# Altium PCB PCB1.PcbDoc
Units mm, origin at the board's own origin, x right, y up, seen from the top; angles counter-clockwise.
Board outline 152.4 x 101.6 mm, 2 copper layers (Top Layer, Bottom Layer); 9 components, 11 nets, 39 pads, 4 vias.
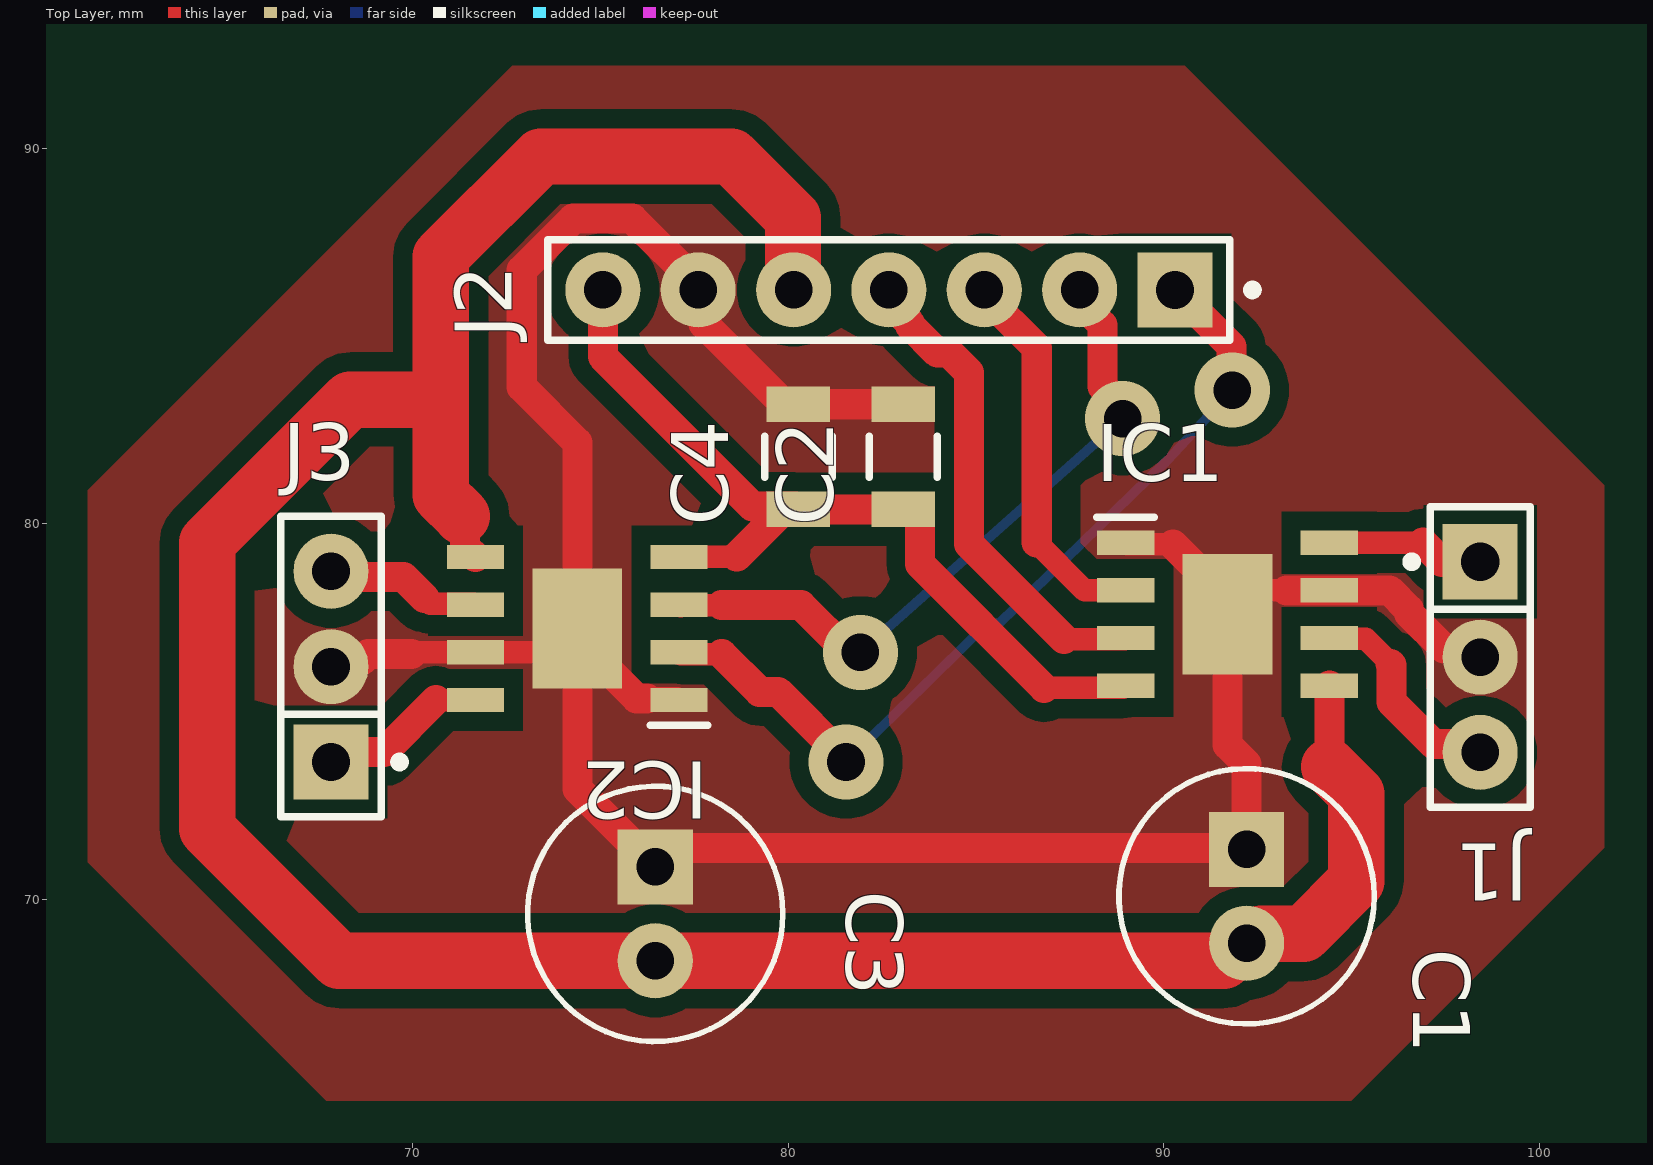
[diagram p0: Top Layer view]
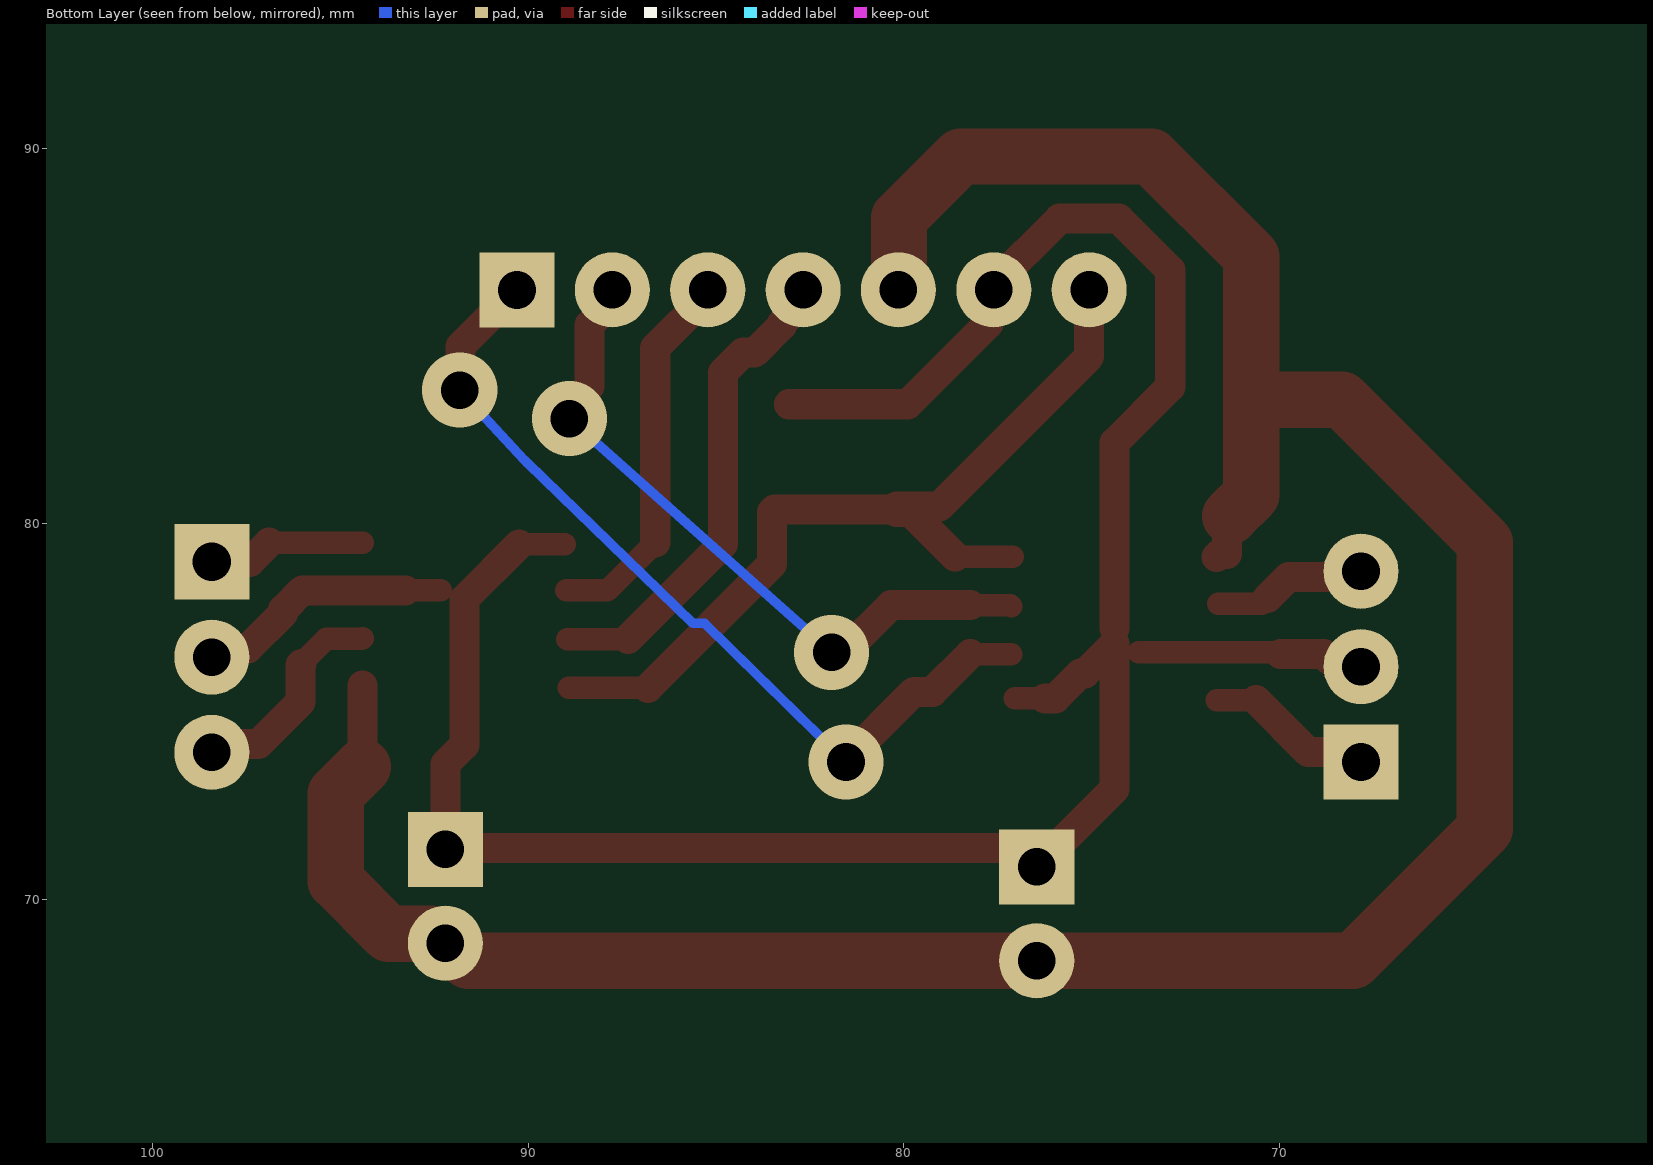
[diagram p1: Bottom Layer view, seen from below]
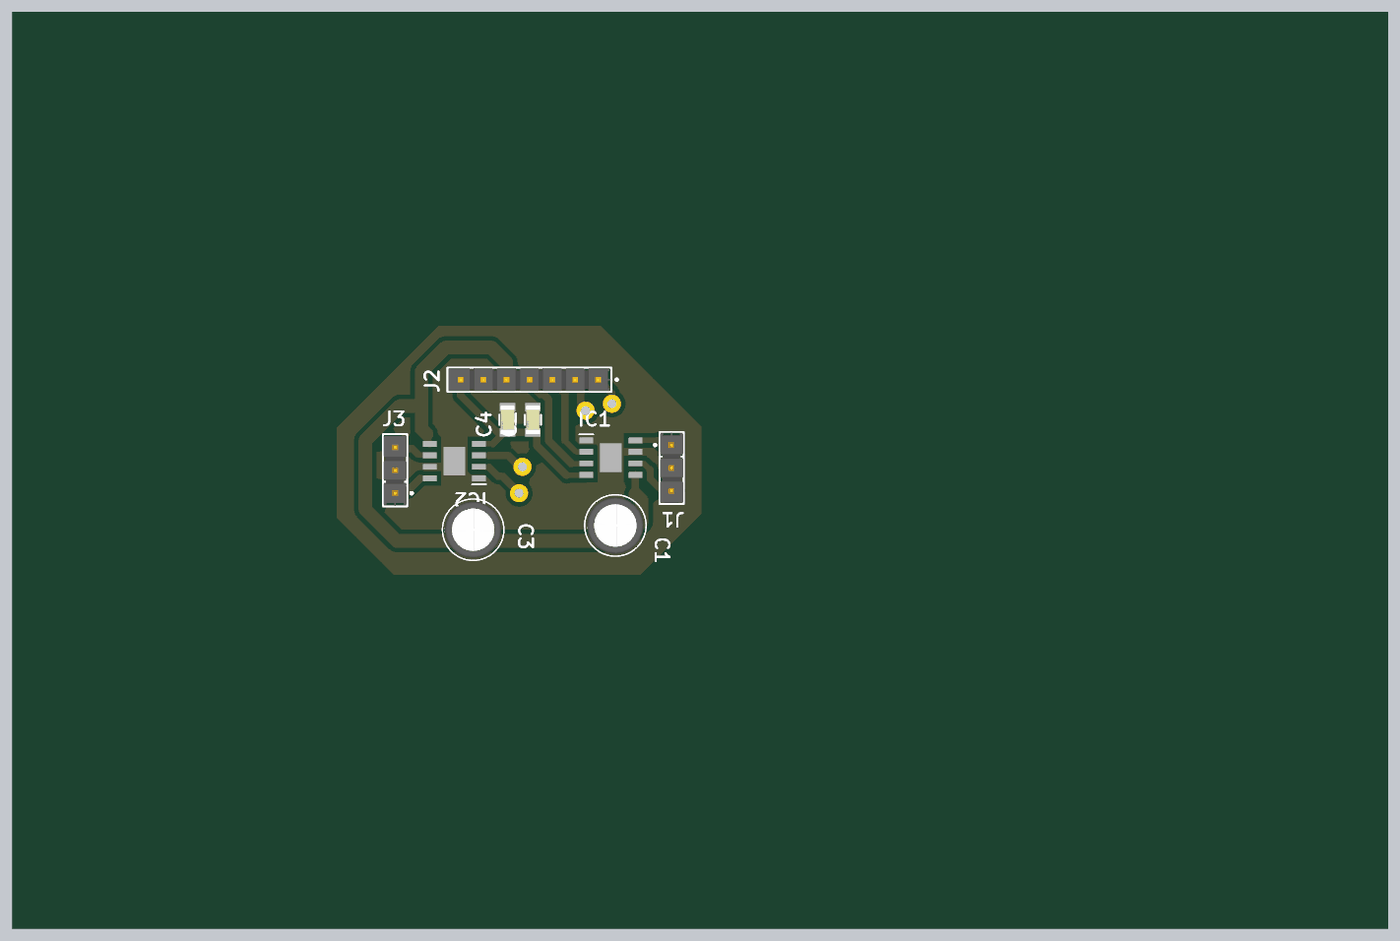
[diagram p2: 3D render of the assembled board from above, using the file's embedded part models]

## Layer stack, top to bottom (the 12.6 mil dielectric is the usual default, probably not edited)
Top Solder: solder mask 0.0102, Solder Resist, Dk 3.5
Top Layer: signal copper 0.0356
Dielectric 1: dielectric 0.32, FR-4, Dk 4.8
Bottom Layer: signal copper 0.0356
Bottom Solder: solder mask 0.0102, Solder Resist, Dk 3.5

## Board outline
25.4,25.4 177.8,25.4 177.8,127 25.4,127

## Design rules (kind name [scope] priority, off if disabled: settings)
Clearance [All] p1: gap=0.5 ignorepadtopadclearanceinfootprint=FALSE
PolygonConnect [All] p1: connectstyle=Direct reliefconductorwidth=0.254 reliefentries=4 polygonreliefangle="90 Angle" airgapwidth=0.254
RoutingVias [All] p1: holewidth=0.711 width=1.27 viastyle="Through Hole" minholewidth=0.711 minwidth=1.27 maxholewidth=0.711 maxwidth=1.27
SolderMaskExpansion [All] p1: expansion=0 istentingtop=FALSE
SupplyNets "Schematic Supply Nets_2" [InNet('+9')] p1: voltage=0.000
SupplyNets "Schematic Supply Nets_1" [InNet('GND')] p2: voltage=0.000
SupplyNets "Schematic Supply Nets" [InNet('+3.3')] p3: voltage=0.000
Width [All] p1: maxlimit=1.5 minlimit=0.254 preferedwidth=0.8 toplayer_minwidth=0.6 bottomlayer_maxwidth=0.254 bottomlayer_prefwidth=0.254 minimp=50.000000 maximp=50.000000 favimp=50.000000
30 further rules are at their usual default settings.

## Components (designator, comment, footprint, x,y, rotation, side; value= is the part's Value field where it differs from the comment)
C1 "ECA1CEN470" FP-RAD-TH-D_6_3_0_5-L_11-MFG 92.202,70.084 r270 top
C2 "C1206C153K5RAC" FP-C1206C-EB-MFG 83.058,81.788 r90 top value="15,000 pF"
C3 "ECA1CEN470" FP-RAD-TH-D_6_3_0_5-L_11-MFG 76.454,69.616 r270 top
C4 "C1206C153K5RAC" FP-C1206C-EB-MFG 80.264,81.788 r90 top value="15,000 pF"
IC1 "TB67H451FNG" SOIC127P600X170-9N 91.694,77.597 r0 top
IC2 "TB67H451FNG" SOIC127P600X170-9N 74.377,77.216 r180 top
J1 "TSW-103-14-G-S" FP-TSW-103-14-G-S-MFG 98.425,76.454 r270 top
J2 "TSW-107-07-G-S" FP-TSW-107-07-G-S-MFG 82.677,86.233 r180 top
J3 "TSW-103-14-G-S" FP-TSW-103-14-G-S-MFG 67.818,76.2 r90 top

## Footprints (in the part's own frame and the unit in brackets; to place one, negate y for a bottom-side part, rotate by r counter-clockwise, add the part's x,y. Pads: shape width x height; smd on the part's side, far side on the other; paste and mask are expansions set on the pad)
FP-C1206C-EB-MFG [mm]
  rect 0.95x1.7 smd paste+0 mask+0: 1(-1.4,0) 2(1.4,0)
  silkscreen extent -0.55,-0.9 0.55,0.9, body extent -2,-1 2,1, height 0.25
FP-RAD-TH-D_6_3_0_5-L_11-MFG [mm]
  rect 2x2 hole 1 paste-2539.97 mask+0: 1(-1.25,0)
  round 2 hole 1 paste-2539.97 mask+0: 2(1.25,0)
  silkscreen extent -3.4,-3.4 3.4,3.4, body extent -3.5,-3.5 3.5,3.5, height 0.25
FP-TSW-103-14-G-S-MFG [mm]
  rect 2x2 hole 1.02 paste-2539.97 mask+0: 1(-2.54,0)
  round 2 hole 1 paste-2539.97 mask+0: 2(0,0) 3(2.54,0)
  silkscreen extent -4,-1.95 4,1.34, body extent -4.1,-1.44 4.1,1.44, height 0.25
FP-TSW-107-07-G-S-MFG [mm]
  rect 2x2 hole 1.02 paste-2539.97 mask+0: 1(-7.62,0)
  round 2 hole 1 paste-2539.97 mask+0: 2(-5.08,0) 3(-2.54,0) 4(0,0) 5(2.54,0) 6(5.08,0) 7(7.62,0)
  silkscreen extent -9.81,-1.34 9.08,1.34, body extent -9.18,-1.44 9.18,1.44, height 0.25
SOIC127P600X170-9N [mm]
  rect 1.525x0.65 smd: 1(-2.712,1.905) 2(-2.712,0.635) 3(-2.712,-0.635) 4(-2.712,-1.905) 5(2.712,-1.905) 6(2.712,-0.635) 7(2.712,0.635) 8(2.712,1.905)
  rect 2.39x3.2 smd: 9(0,0)
  silkscreen extent -3.47,2.58 -1.95,2.58, body extent 0,0 0,0

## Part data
C1 C3: library part CMP-05427-001931-1, "Aluminum Electrolytic Capacitors (Radial Lead Type) 47uF ±20% 16V", Capacitance=47uF, Case/Package=Radial, Max Operating Temperature=105°C, Min Operating Temperature=-40°C, Package Quantity=200, Ripple Current=100mA, Tolerance=20%, Voltage Rating (DC)=16V
C2 C4: library part CMP-03020-027494-1, "C1206 15,000 pF X7R 10.00% 50 V", Capacitance="15,000 pF", Manufacturer=KEMET, Package=C1206C-EB, Temperature="-55°C to +150°C", Temperature Characteristic=X7R, Temperature Coefficient=15%, Temperature Range High=+150°C, Temperature Range Low=-55°C, Tolerance=0.1, Voltage Rating="50 V"
IC1 IC2: "Integrated Circuit", Manufacturer_Name=Toshiba, Mouser Part Number=N/A
J1 J3: library part CMP-02766-001743-1, "CONN HEADER VERT 3POS 2.54MM", Color=Black, Flammability Rating="UL94 V-0", Max Current Rating=7.6A, Max Operating Temperature=125°C, Max Voltage Rating (AC)=550V, Min Operating Temperature=-55°C, Package Quantity=1
J2: library part CMP-02766-000065-1, "CONN HEADER VERT 7POS 2.54MM", Manufacturer=SAMTEC, Package=0, Temperature="-55°C to +125°C", Temperature Range High=+125°C, Temperature Range Low=-55°C

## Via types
v1: diameter 2, hole 1, Top Layer to Bottom Layer, 4 vias

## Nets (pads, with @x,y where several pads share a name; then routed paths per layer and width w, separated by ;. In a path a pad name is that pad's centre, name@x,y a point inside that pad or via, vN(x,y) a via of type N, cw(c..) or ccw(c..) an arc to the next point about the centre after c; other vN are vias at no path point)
+3.3: C2.1 C4.1 IC1.4 IC2.4 J2.7 | length 23.7
  Top Layer w0.6: IC2.4 78.607,79.121 78.622,79.136 ; 86.807,75.632 IC1.4@88.922,75.632
  Top Layer w0.8: J2.7 75.057,84.455 79.049,80.463 80.189,80.463 C4.1 C2.1 83.433,80.388 83.508,80.313 83.508,78.931 86.807,75.632 ; 78.622,79.136 78.637,79.136 79.814,80.313 C4.1@80.189,80.313
+9: C1.2 C3.2 IC1.5 IC2.5 J2.5 | length 75
  Top Layer w0.8: 70.007,83.312 70.739,83.312 ; 71.302,80.208 71.382,80.129 71.382,79.196 71.59,79.196 IC2.5 ; 94.406,73.533 IC1.5
  Top Layer w1.5: 70.007,83.312 68.326,83.312 64.519,79.505 64.519,71.879 68.032,68.366 91.599,68.366 92.067,68.834 C1.2 ; 71.302,80.209 70.739,80.772 70.739,83.312 70.739,87.122 73.406,89.789 78.486,89.789 80.124,88.151 80.124,86.265 J2.5@80.137,86.252 ; C1.2@92.587,69.084 93.72,69.084 95.123,70.487 95.123,72.816 94.406,73.533
GND: C1.1 C2.2 C3.1 C4.2 IC1.1 IC1.7 IC1.9 IC2.1 IC2.7 IC2.9 J1.2 J2.6 J3.2 | length 72.6
  Top Layer w0.6: 69.962,76.581 IC2.7 IC2.9@73.742,76.581 ; 76.237,75.356 IC2.1@77.044,75.356 ; IC1.1@89.027,79.457 90.239,79.457 ; IC1.9@92.329,78.232 93.271,78.232
  Top Layer w0.8: J3.2 67.965,76.347 68.621,76.347 68.81,76.536 69.962,76.536 ; IC2.9 74.377,82.171 72.898,83.65 72.898,86.761 74.27,88.133 75.844,88.133 77.597,86.38 J2.6 77.744,86.086 77.744,85.333 79.889,83.188 C4.2 C2.2 ; 76.237,75.356 75.954,75.356 75.294,76.016 75.172,76.016 74.377,76.811 74.377,72.943 C3.1 76.962,71.374 92.002,71.374 92.042,71.334 C1.1 92.202,73.612 91.694,74.12 IC1.9 91.694,78.002 90.239,79.457 ; 93.271,78.232 IC1.7 96.012,78.232 96.525,77.719 96.525,77.621 97.463,76.684 98.195,76.684 J1.2
MOTOR1A: IC1.3 J2.4 | length 13
  Top Layer w0.6: 87.346,76.932 IC1.3@88.952,76.932
  Top Layer w0.8: J2.4 82.677,85.908 83.242,85.343 83.242,85.287 83.966,84.563 84.281,84.563 84.808,84.036 84.808,79.47 87.346,76.932
MOTOR1B: IC1.2 J2.3 | length 10.2
  Top Layer w0.6: 86.614,79.51 87.892,78.232 IC1.2
  Top Layer w0.8: J2.3 85.217,86.086 86.614,84.689 86.614,79.51
MOTOR2A: IC2.3 J2.2 | length 18.6
  Top Layer w0.6: IC2.3@77.134,77.806 77.164,77.836 78.224,77.836
  Top Layer w0.8: 78.224,77.836 80.335,77.836 81.59,76.581 v1(81.915,76.581) ; J2.2 87.757,85.908 88.366,85.299 88.366,83.663 88.9,83.129 v1(88.9,82.804)
  Bottom Layer w0.254: v1(81.915,76.581) v1(88.9,82.804)
MOTOR2B: IC2.2 J2.1 | length 23.3
  Top Layer w0.6: IC2.2@77.134,76.536 78.224,76.536
  Top Layer w0.8: 78.224,76.536 79.232,75.528 79.725,75.528 81.534,73.719 v1(81.534,73.66) ; J2.1 91.8,84.73 91.8,83.587 v1(91.821,83.566)
  Bottom Layer w0.254: v1(81.534,73.66) 85.294,77.355 85.504,77.355 85.61,77.355 90.032,81.635 ccw(c88.9,82.804) 90.094,81.699 v1(91.821,83.566)
OUT2BOC1: IC2.6 J3.3 | length 4.2
  Top Layer w0.6: 70.313,78.025 70.462,77.876 IC2.6@71.62,77.876
  Top Layer w0.8: J3.3 67.965,78.593 69.745,78.593 70.313,78.025
OUT2BOC2: IC2.8 J3.1 | length 4.5
  Top Layer w0.6: 70.612,75.311 IC2.8
  Top Layer w0.8: J3.1 68.08,73.922 69.223,73.922 70.612,75.311
OUTBOC1: IC1.6 J1.3 | length 5.9
  Top Layer w0.6: IC1.6 94.431,76.937 95.38,76.937 96.036,76.281 96.036,76.272
  Top Layer w0.8: 96.036,76.272 96.069,76.239 96.069,75.254 97.179,74.144 98.195,74.144 J1.3
OUTBOC2: IC1.8 J1.1 | length 4.2
  Top Layer w0.6: IC1.8 96.901,79.502
  Top Layer w0.8: 96.901,79.502 97.409,78.994 J1.1

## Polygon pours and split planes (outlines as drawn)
GND on Top Layer "GND_L01_P000" (solid, pour order 0): 67.691,64.643 61.341,70.993 61.341,80.899 72.644,92.202 90.551,92.202 101.727,81.026 101.727,71.374 94.996,64.643

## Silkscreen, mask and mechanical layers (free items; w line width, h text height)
Mechanical 1:
  lines w2: 61.341,70.993 61.341,80.899 72.644,92.202 90.551,92.202 101.727,81.026 101.727,71.374 94.996,64.643 67.691,64.643 61.341,70.993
